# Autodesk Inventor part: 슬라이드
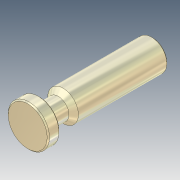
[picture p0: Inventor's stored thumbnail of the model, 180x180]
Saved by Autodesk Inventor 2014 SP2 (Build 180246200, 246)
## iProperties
Company: 한국ATC센터
Created: 2014-11
Part Number: 슬라이드
Document SubType Name: Modeling
Designer: KYOUNG IL JANG
Density: 7.86 g/cm^3
Material: 강, 연강
Mass: 436.103 g
Surface Area: 105.764 cm^2
Volume: 55.4838 cm^3
Appearance: 티타늄 - 광택
Author: KYOUNG IL JANG
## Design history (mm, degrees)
sketch "스케치1"
  geometry: L1 (19, 106.5)-(-19, 106.5) reference; L2 (0, 106.5)-(0, 212.5); L3 (0, 212.5)-(-13, 212.5); L4 (-13, 212.5)-(-13, 136.5); L5 (-9, 116.5)-(-17.5, 116.5); L6 (-17.5, 116.5)-(-17.5, 106.5); L7 (-17.5, 106.5)-(0, 106.5); L8 (-9, 116.5)-(-9, 132.5); L9 (-9, 132.5)-(-13, 136.5); 1 further point
  constraints: 18 end point, 3 perpendicular, 1 collinear, 1 horizontal, 1 midpoint, 1 parallel, 2 other
  dimensions: "d0" = 10 distance between parallel lines of L5 L7; "d1" = 35 diameter of L6 L2; "d2" = 106 distance of L2.start L2.end; "d3" = 135 deg angle of L9 L4; "d4" = 18 diameter of L8 L2; "d5" = 30 distance from line of L4.end L7; "d11" = 26 diameter of L4 L2
revolve "회전1" sketch "스케치1" stored, may be unused: angle "d6" = 90 deg
chamfer "모따기1" distance "d7" = 1; stored, may be unused: second distance "d8" = 2, angle "d9" = 45 deg
fillet "모깎기1" dims "d10" = 2
node "솔리드1"
